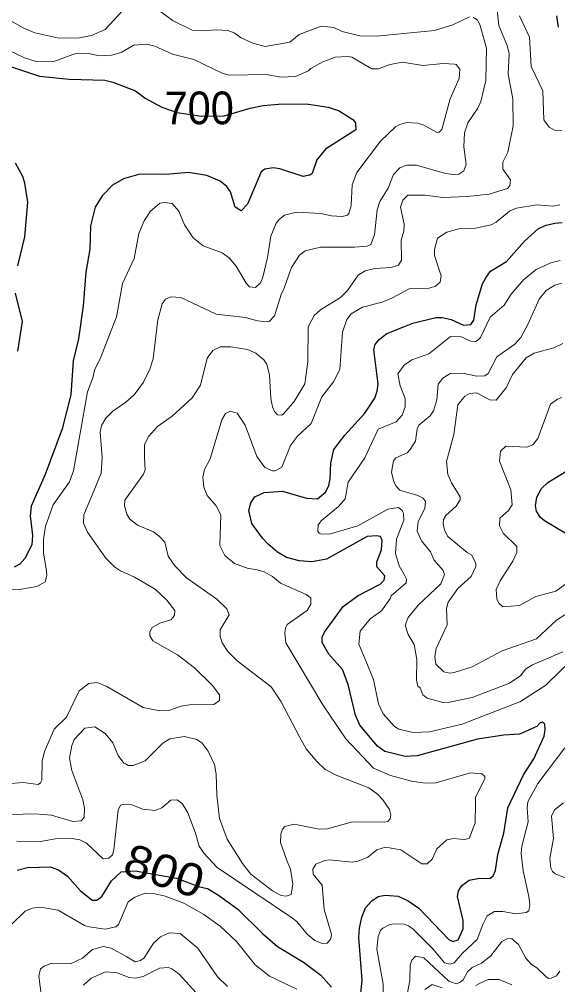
# Model space of a CAD drawing. Extents: x 294.2 to 320.3, y 7482.7 to 7510.7.
# Drawn here: x 316.982 to 318.3, y 7497.059 to 7499.421 of the extents above; entities that cross this region are included whole.
import ezdxf
from ezdxf.enums import TextEntityAlignment as Align

# ---------------------------------------------------------------- set-up
doc = ezdxf.new("R2010")
doc.units = 0
doc.header["$LTSCALE"] = 0.032
doc.layers.add('1', color=7, linetype='Continuous', lineweight=25)
doc.layers.add('2', color=7, linetype='Continuous', lineweight=13)
doc.layers.add('61', color=7, linetype='Continuous')

msp = doc.modelspace()

# ---------------------------------------------------------------- linework, layer by layer
at = {"layer": '1'}
for points in [[(318.3019, 7499.4013), (318.2974, 7499.4294)], [(316.9387, 7499.313), (317.0313, 7499.2818), (317.104, 7499.2742), (317.1916, 7499.2715), (317.2115, 7499.2672), (317.2664, 7499.2457), (317.2902, 7499.2274), (317.3313, 7499.2059), (317.3685, 7499.1924), (317.4284, 7499.1838), (317.4833, 7499.1843), (317.5471, 7499.2031), (317.5793, 7499.2096), (317.6264, 7499.2139), (317.6896, 7499.2128), (317.7384, 7499.2058), (317.765, 7499.1967), (317.7983, 7499.1757), (317.805, 7499.1671), (317.8055, 7499.1504), (317.7318, 7499.1031), (317.7102, 7499.0768), (317.6985, 7499.0434), (317.6935, 7499.0391), (317.6769, 7499.0364), (317.6197, 7499.0552), (317.6031, 7499.0574), (317.5831, 7499.0542), (317.5742, 7499.0472), (317.541, 7498.9686), (317.5249, 7498.9525), (317.5105, 7498.9611), (317.4989, 7498.9987), (317.49, 7499.0116), (317.4739, 7499.0245), (317.4412, 7499.039), (317.3963, 7499.046), (317.3408, 7499.0411), (317.2775, 7499.0421), (317.2375, 7499.0308), (317.2103, 7499.0152), (317.1853, 7498.9889), (317.1682, 7498.9614), (317.1565, 7498.9152), (317.1548, 7498.8582), (317.1454, 7498.8023), (317.1382, 7498.7195), (317.1271, 7498.6388), (317.1138, 7498.5851), (317.1083, 7498.5023), (317.0875, 7498.4193), (317.0452, 7498.3073), (317.0109, 7498.2299), (317.0092, 7498.2063), (317.0148, 7498.1584), (317.0131, 7498.1353), (316.9954, 7498.1014), (316.9837, 7498.088), (316.9699, 7498.0804)], [(316.9785, 7498.8178), (316.9962, 7498.8883), (317.0034, 7498.9738), (316.9962, 7499.0195), (316.9911, 7499.0361), (316.9731, 7499.0689)], [(318.1237, 7498.7884), (318.1353, 7498.8046), (318.1741, 7498.8282), (318.2185, 7498.8777), (318.2529, 7498.9089), (318.2718, 7498.9175), (318.2923, 7498.9224)], [(318.2923, 7498.9224), (318.3106, 7498.924)], [(317.909, 7497.2754), (317.9334, 7497.2646), (317.96, 7497.2463), (318.0333, 7497.1694), (318.0427, 7497.1651), (318.056, 7497.1689), (318.0682, 7497.1958), (318.0682, 7497.2162), (318.0549, 7497.2748), (318.0566, 7497.2888), (318.0655, 7497.3022), (318.0827, 7497.3146), (318.1043, 7497.3189), (318.1342, 7497.32), (318.142, 7497.3254), (318.1475, 7497.3388), (318.1536, 7497.3776), (318.1675, 7497.4297), (318.178, 7497.4921), (318.2158, 7497.5728), (318.2413, 7497.612), (318.2663, 7497.6669), (318.269, 7497.6836), (318.2679, 7497.6965), (318.2624, 7497.7013), (318.2557, 7497.6992), (318.2485, 7497.6906), (318.2064, 7497.6717), (318.1681, 7497.6696), (318.1032, 7497.6599), (317.9562, 7497.6191), (317.9263, 7497.6175), (317.8974, 7497.6245), (317.8763, 7497.6299), (317.8586, 7497.6428), (317.8153, 7497.6939), (317.8048, 7497.7181), (317.787, 7497.7934), (317.7731, 7497.83), (317.7393, 7497.8676), (317.7232, 7497.8966), (317.7232, 7497.9095), (317.7288, 7497.9219), (317.7744, 7497.9843), (317.8115, 7498.0112), (317.8654, 7498.0392), (317.8748, 7498.0489), (317.877, 7498.0591), (317.8571, 7498.0817), (317.8571, 7498.0936), (317.8682, 7498.1227), (317.8698, 7498.1457), (317.8665, 7498.1554), (317.8565, 7498.157), (317.8338, 7498.1554), (317.7339, 7498.1), (317.6979, 7498.0936), (317.6674, 7498.0957), (317.6363, 7498.1043), (317.6141, 7498.1172), (317.5914, 7498.1371), (317.577, 7498.1516), (317.5514, 7498.1871), (317.5442, 7498.2194), (317.5492, 7498.2382), (317.5586, 7498.2522), (317.5813, 7498.2635), (317.6263, 7498.2661), (317.685, 7498.2495), (317.7122, 7498.2479), (317.7327, 7498.2645), (317.7399, 7498.2801), (317.7432, 7498.2968), (317.7443, 7498.3349), (317.7521, 7498.3683), (317.7787, 7498.4033), (317.8281, 7498.4571), (317.8519, 7498.4942), (317.858, 7498.5114), (317.8602, 7498.5292), (317.8497, 7498.612), (317.853, 7498.6249), (317.8625, 7498.6373), (317.8819, 7498.6523), (317.9246, 7498.6695), (317.9456, 7498.6776), (318.0011, 7498.691), (318.0171, 7498.691), (318.0388, 7498.6862), (318.0693, 7498.6722), (318.087, 7498.6744), (318.0948, 7498.6846), (318.1004, 7498.7222), (318.1159, 7498.7739), (318.1237, 7498.7884)], [(316.9786, 7498.6092), (316.9897, 7498.6813), (316.973, 7498.7512)], [(318.3507, 7498.1441), (318.2674, 7498.1939), (318.2572, 7498.2028), (318.2476, 7498.2175), (318.2451, 7498.2303), (318.249, 7498.2514), (318.2603, 7498.2726), (318.2754, 7498.2877), (318.3283, 7498.3202)], [(316.9767, 7497.3393), (317.0022, 7497.3458), (317.0577, 7497.3473), (317.0782, 7497.3403), (317.0999, 7497.3248), (317.131, 7497.2898), (317.1609, 7497.2661), (317.172, 7497.2661), (317.1842, 7497.2753), (317.2081, 7497.3129), (317.2319, 7497.3355), (317.2657, 7497.3377), (317.3666, 7497.3194), (317.4232, 7497.2984), (317.4425, 7497.2949), (317.4696, 7497.2782), (317.5168, 7497.2437), (317.5772, 7497.1846), (317.6144, 7497.1528), (317.6776, 7497.1146), (317.7198, 7497.0824), (317.7458, 7497.0528)], [(317.8147, 7497.1974), (317.8202, 7497.2243), (317.8296, 7497.2474), (317.8452, 7497.2646), (317.8607, 7497.2748), (317.8779, 7497.278), (317.909, 7497.2754)], [(317.8174, 7497.0307), (317.8213, 7497.07), (317.813, 7497.1748), (317.8147, 7497.1974)]]:
    msp.add_lwpolyline(points, dxfattribs=at)
at = {"layer": '2'}
for points in [[(318.1493, 7499.4651), (318.1557, 7499.4057), (318.1758, 7499.3567), (318.1806, 7499.3362), (318.1787, 7499.2864), (318.1902, 7499.2263), (318.1908, 7499.1599), (318.1774, 7499.0954), (318.1651, 7499.0713), (318.1656, 7499.0541), (318.184, 7499.0279), (318.1823, 7499.0134), (318.1771, 7499.0068), (318.1318, 7498.9928), (318.0785, 7498.9875), (318.0184, 7498.9849), (317.975, 7498.9907), (317.9331, 7498.9907), (317.9205, 7498.9785), (317.9153, 7498.9612), (317.9239, 7498.9195), (317.9228, 7498.9024), (317.9165, 7498.8807), (317.9176, 7498.8317), (317.9102, 7498.8189), (317.8924, 7498.8133), (317.8524, 7498.8113), (317.8282, 7498.8056), (317.8115, 7498.7947), (317.7854, 7498.7577), (317.7682, 7498.7398), (317.719, 7498.7104), (317.7037, 7498.6964), (317.6889, 7498.6683), (317.6883, 7498.5828), (317.6813, 7498.5291), (317.6545, 7498.4857), (317.6296, 7498.4563)], [(317.2337, 7499.4408), (317.1922, 7499.3955), (317.1591, 7499.3808), (317.1297, 7499.3757), (317.0786, 7499.3744), (317.0199, 7499.3879), (316.9918, 7499.4), (316.9618, 7499.4166)], [(318.0836, 7499.4268), (318.0427, 7499.407), (317.998, 7499.3936), (317.8563, 7499.3795), (317.8154, 7499.3802), (317.772, 7499.391), (317.7516, 7499.4006), (317.7209, 7499.4038), (317.6673, 7499.3839), (317.6443, 7499.3644), (317.5842, 7499.354), (317.5536, 7499.3623), (317.5249, 7499.3757), (317.5077, 7499.3879), (317.4929, 7499.393), (317.4642, 7499.3948), (317.4285, 7499.3923), (317.4055, 7499.3942), (317.3589, 7499.4172), (317.311, 7499.4523)], [(318.0797, 7499.1676), (318.104, 7499.2034), (318.1116, 7499.22), (318.1238, 7499.271), (318.1257, 7499.3502), (318.1091, 7499.4076), (318.1034, 7499.4185)], [(318.1034, 7499.4185), (318.0925, 7499.4262)], [(318.3102, 7499.1483), (318.2918, 7499.1499), (318.2792, 7499.1566), (318.266, 7499.1744), (318.2631, 7499.2459), (318.235, 7499.3055), (318.231, 7499.377), (318.2061, 7499.4293)], [(317.8664, 7499.1229), (317.9029, 7499.1573), (317.9137, 7499.1637), (317.9303, 7499.1682), (317.9571, 7499.1663), (317.9725, 7499.1618), (318.0044, 7499.144), (318.0095, 7499.1446), (318.0165, 7499.151), (318.0363, 7499.2263), (318.0587, 7499.2761), (318.0599, 7499.2984), (318.051, 7499.31), (318.0472, 7499.3106), (318.0197, 7499.3125), (317.9699, 7499.308), (317.9201, 7499.3157), (317.8895, 7499.31), (317.8607, 7499.2998), (317.8448, 7499.2998), (317.7956, 7499.3278), (317.786, 7499.3297), (317.7554, 7499.3284), (317.7247, 7499.3164), (317.6953, 7499.3004), (317.6902, 7499.2946), (317.6583, 7499.2806), (317.6226, 7499.2793), (317.5868, 7499.2857), (317.4949, 7499.2838), (317.4783, 7499.2889), (317.4093, 7499.3221), (317.357, 7499.3355), (317.3142, 7499.3553), (317.2944, 7499.3598), (317.2625, 7499.3572), (317.2318, 7499.3393), (317.2076, 7499.333), (317.1782, 7499.331), (317.1514, 7499.3374), (317.1226, 7499.3381), (317.0664, 7499.3173), (317.021, 7499.3184), (316.9951, 7499.3268), (316.9561, 7499.3455)], [(316.9624, 7497.5516), (316.9918, 7497.5535), (317.0281, 7497.5491), (317.0339, 7497.5529), (317.0371, 7497.5599), (317.0384, 7497.6059), (317.0436, 7497.6296), (317.0677, 7497.6842), (317.0981, 7497.7137), (317.1284, 7497.7783), (317.1527, 7497.7961), (317.1731, 7497.7981), (317.1961, 7497.7884), (317.2855, 7497.7374), (317.3263, 7497.7291), (317.348, 7497.7297), (317.3787, 7497.7406), (317.3991, 7497.7437), (317.4585, 7497.7444), (317.4719, 7497.7546), (317.4725, 7497.7681), (317.4546, 7497.7917), (317.4112, 7497.8344), (317.3697, 7497.8657), (317.3091, 7497.9002), (317.3014, 7497.9124), (317.3014, 7497.9225), (317.3072, 7497.9328), (317.3263, 7497.9436), (317.3531, 7497.9519), (317.3621, 7497.9621), (317.3627, 7497.9749), (317.3436, 7497.9998), (317.3148, 7498.0266), (317.2638, 7498.056), (317.2299, 7498.0713), (317.2152, 7498.0815), (317.1942, 7498.1026), (317.1495, 7498.1665), (317.1393, 7498.1882), (317.1399, 7498.2086), (317.1577, 7498.2495), (317.1827, 7498.3108), (317.1852, 7498.3491), (317.1801, 7498.4104), (317.1833, 7498.427), (317.1942, 7498.4454), (317.2108, 7498.4621), (317.2427, 7498.4838), (317.2637, 7498.5023), (317.2861, 7498.533), (317.3014, 7498.5649), (317.3097, 7498.5904), (317.321, 7498.6859), (317.3319, 7498.7243), (317.3397, 7498.7359), (317.3531, 7498.7417), (317.3774, 7498.7398), (317.4642, 7498.6996), (317.5358, 7498.6912), (317.5655, 7498.6828), (317.5885, 7498.6806), (317.5937, 7498.6812), (317.6069, 7498.6951), (317.6235, 7498.7497), (317.6287, 7498.7586), (317.6481, 7498.8139), (317.6679, 7498.8439), (317.6819, 7498.8547), (317.7196, 7498.8636), (317.8026, 7498.863), (317.8333, 7498.8656), (317.8422, 7498.87), (317.8518, 7498.8931), (317.8582, 7498.9543), (317.8646, 7498.9748), (317.885, 7499.008), (317.8977, 7499.0412), (317.9137, 7499.0571), (317.9303, 7499.0635), (317.9546, 7499.0635), (318.0248, 7499.0437), (318.0443, 7499.0409), (318.0581, 7499.0421), (318.0702, 7499.0499), (318.0754, 7499.0654), (318.0702, 7499.1089), (318.072, 7499.1433), (318.0797, 7499.1676)], [(317.7723, 7498.9385), (317.785, 7498.9419), (317.789, 7498.9458), (317.7947, 7498.9653), (317.7969, 7499.0156), (317.8084, 7499.0463), (317.8664, 7499.1229)], [(316.965, 7498.026), (316.9879, 7498.0266), (317.025, 7498.033), (317.0454, 7498.0445), (317.0499, 7498.0605), (317.0486, 7498.0707), (317.0415, 7498.1154), (317.0415, 7498.1486), (317.046, 7498.1805), (317.0652, 7498.2329), (317.1048, 7498.2891), (317.115, 7498.3159), (317.1492, 7498.5092), (317.1624, 7498.5438), (317.1669, 7498.5647), (317.1802, 7498.5903), (317.2197, 7498.6926), (317.235, 7498.7743), (317.2631, 7498.8356), (317.2746, 7498.8969), (317.288, 7498.9275), (317.3021, 7498.9505), (317.3263, 7498.9709), (317.3378, 7498.9728), (317.3563, 7498.9703), (317.3723, 7498.9516), (317.3866, 7498.9181), (317.4073, 7498.8864), (317.4323, 7498.8669), (317.4783, 7498.8496), (317.4961, 7498.8375), (317.5127, 7498.8171), (317.5377, 7498.7749), (317.5453, 7498.7666), (317.56, 7498.7647), (317.5728, 7498.7762), (317.5785, 7498.7896), (317.59, 7498.8381), (317.5977, 7498.8905), (317.6111, 7498.9224), (317.6187, 7498.932), (317.6308, 7498.9415), (317.6609, 7498.9486), (317.7203, 7498.946), (317.7465, 7498.9402), (317.7723, 7498.9385)], [(317.4751, 7498.2086), (317.4636, 7498.2309), (317.4419, 7498.2559), (317.4336, 7498.2763), (317.431, 7498.3005), (317.4355, 7498.3197), (317.4489, 7498.3452), (317.4776, 7498.441), (317.4866, 7498.4563), (317.498, 7498.4621), (317.5153, 7498.4576), (317.5351, 7498.4282), (317.5632, 7498.3516), (317.583, 7498.3242), (317.6015, 7498.3158), (317.6085, 7498.3165), (317.6245, 7498.3254), (317.6455, 7498.3784), (317.6634, 7498.4008), (317.6966, 7498.4321), (317.7228, 7498.4972), (317.7515, 7498.5342), (317.7662, 7498.5642), (317.7732, 7498.6555), (317.7834, 7498.6862), (317.7943, 7498.7002), (317.8218, 7498.7162), (317.8703, 7498.729), (317.8958, 7498.7391), (317.9363, 7498.7618), (317.9852, 7498.7628), (318.0005, 7498.7679), (318.012, 7498.7781), (318.0146, 7498.7928), (317.9986, 7498.8432), (317.9986, 7498.8573), (318.0056, 7498.8854), (318.0287, 7498.9001), (318.058, 7498.9083), (318.0989, 7498.9096), (318.1372, 7498.9179), (318.1493, 7498.9243), (318.1819, 7498.9511), (318.1985, 7498.9588), (318.2483, 7498.9671), (318.2879, 7498.9639), (318.3051, 7498.9665)], [(318.3434, 7497.8625), (318.2706, 7497.7917), (318.209, 7497.752), (318.0661, 7497.6966), (317.9863, 7497.6779), (317.9461, 7497.6762), (317.911, 7497.6846), (317.9003, 7497.6908), (317.8728, 7497.7221), (317.8613, 7497.7463), (317.8492, 7497.8057), (317.8301, 7497.8511), (317.8128, 7497.8919), (317.8167, 7497.9238), (317.8409, 7497.9538), (317.8684, 7497.9736), (317.8907, 7498.0049), (317.8918, 7498.0105), (317.9289, 7498.0421), (317.9294, 7498.0513), (317.9239, 7498.0628), (317.9119, 7498.0839), (317.9027, 7498.1137), (317.9055, 7498.1488), (317.9228, 7498.1956), (317.9226, 7498.2124), (317.9195, 7498.2195), (317.9099, 7498.2264), (317.8837, 7498.2226), (317.8103, 7498.1817), (317.7438, 7498.1621), (317.7214, 7498.161), (317.7162, 7498.1637), (317.7128, 7498.1676), (317.7134, 7498.1838), (317.722, 7498.1944), (317.7633, 7498.2286), (317.7793, 7498.2475), (317.7868, 7498.2887), (317.8281, 7498.3478), (317.8601, 7498.4181), (317.9041, 7498.4359), (317.9188, 7498.4525), (317.9265, 7498.4729), (317.9265, 7498.4934), (317.9144, 7498.524), (317.9086, 7498.5534), (317.9239, 7498.5744), (317.9431, 7498.5878), (317.984, 7498.6025), (318.0376, 7498.6447), (318.0631, 7498.644), (318.0874, 7498.6332), (318.0982, 7498.6325), (318.1052, 7498.637), (318.111, 7498.6421), (318.1346, 7498.6919), (318.1685, 7498.7213), (318.1857, 7498.7481), (318.217, 7498.7839), (318.247, 7498.8087), (318.2828, 7498.8247), (318.3058, 7498.8311)], [(318.1946, 7498.6261), (318.2093, 7498.6421), (318.2278, 7498.676), (318.254, 7498.736), (318.2713, 7498.7571), (318.293, 7498.7704), (318.3096, 7498.7749)], [(317.5945, 7498.5502), (317.5881, 7498.577), (317.581, 7498.5878), (317.5613, 7498.6038), (317.5409, 7498.6128), (317.5, 7498.6197), (317.4744, 7498.6198), (317.4559, 7498.6102), (317.4419, 7498.5917), (317.4259, 7498.5259), (317.4049, 7498.4946), (317.3563, 7498.4499), (317.3206, 7498.425), (317.2982, 7498.4001), (317.2887, 7498.3797), (317.2887, 7498.3491), (317.2899, 7498.3184), (317.2861, 7498.3082), (317.2407, 7498.2443), (317.2395, 7498.2303), (317.2452, 7498.2099), (317.2529, 7498.1983), (317.2714, 7498.183), (317.311, 7498.1671), (317.3244, 7498.1562), (317.3384, 7498.1416), (317.3467, 7498.1077), (317.3627, 7498.0841), (317.3915, 7498.0547), (317.4655, 7498.0023), (317.4904, 7497.9787), (317.4955, 7497.9641), (317.4738, 7497.927), (317.4738, 7497.9111), (317.4783, 7497.8957), (317.4923, 7497.874), (317.5153, 7497.8517), (317.5983, 7497.7878), (317.6232, 7497.7515), (317.6679, 7497.6659), (317.6845, 7497.6365), (317.71, 7497.6052), (317.7311, 7497.5854), (317.7579, 7497.5714), (317.8377, 7497.5407), (317.8588, 7497.5254), (317.8716, 7497.5114), (317.8882, 7497.4878), (317.8914, 7497.4744), (317.8901, 7497.4647), (317.8837, 7497.4584), (317.8754, 7497.4564), (317.7975, 7497.4577), (317.7362, 7497.4405), (317.7158, 7497.4398), (317.6545, 7497.452), (317.6322, 7497.4462), (317.6264, 7497.4399), (317.6219, 7497.4271), (317.6213, 7497.4067), (317.6372, 7497.3626), (317.6455, 7497.3422), (317.6518, 7497.3049), (317.6472, 7497.2799), (317.6351, 7497.276), (317.6231, 7497.2771), (317.6021, 7497.2892), (317.5489, 7497.3295), (317.5288, 7497.3556), (317.4909, 7497.4155), (317.4725, 7497.4654), (317.4655, 7497.5229), (317.4642, 7497.5739), (317.4598, 7497.5982), (317.4444, 7497.6301), (317.4298, 7497.6499), (317.417, 7497.6589), (317.3863, 7497.6665), (317.3506, 7497.6607), (317.3333, 7497.6499), (317.2906, 7497.6071), (317.2612, 7497.595), (317.249, 7497.595), (317.2427, 7497.5995), (317.2382, 7497.6007), (317.2241, 7497.6199), (317.2108, 7497.6506), (317.1922, 7497.6735), (317.1673, 7497.6901), (317.1425, 7497.687), (317.1162, 7497.6589), (317.1105, 7497.6442), (317.1054, 7497.6135), (317.1112, 7497.5829), (317.138, 7497.5114)], [(318.3121, 7497.8734), (318.2378, 7497.8418), (318.2212, 7497.8307), (318.2091, 7497.8154), (318.1821, 7497.7964), (318.0903, 7497.7619), (318.0346, 7497.7502), (318.0185, 7497.7497), (317.9807, 7497.7597), (317.9699, 7497.7681), (317.9629, 7497.7853), (317.9571, 7497.7897), (317.9539, 7497.8044), (317.9552, 7497.8549), (317.9482, 7497.8912), (317.9341, 7497.9162), (317.9271, 7497.9366), (317.9277, 7497.943), (317.9335, 7497.9576), (317.9584, 7497.9877), (318.014, 7498.0394), (318.0229, 7498.0624), (318.0197, 7498.0726), (317.9974, 7498.0975), (317.9884, 7498.1179), (317.9667, 7498.1448), (317.9558, 7498.169), (317.9584, 7498.192), (317.9744, 7498.2239), (317.9763, 7498.2412), (317.9705, 7498.2495), (317.9571, 7498.2558), (317.9137, 7498.2693), (317.9035, 7498.2795), (317.8978, 7498.2929), (317.8927, 7498.3133), (317.8978, 7498.3408), (317.9035, 7498.3477), (317.931, 7498.3605), (317.9386, 7498.3682), (317.952, 7498.3886), (317.9558, 7498.4193), (317.9597, 7498.4276), (317.9878, 7498.4506), (317.9961, 7498.4627), (318.0043, 7498.4895), (318.0076, 7498.5285), (318.0184, 7498.5431), (318.0363, 7498.5546), (318.067, 7498.5553), (318.1017, 7498.5477), (318.1218, 7498.5488), (318.1298, 7498.5539), (318.1511, 7498.5951), (318.1946, 7498.6261)], [(318.3172, 7497.9641), (318.2968, 7497.9506), (318.2476, 7497.9053), (318.164, 7497.876), (318.09, 7497.837), (318.0465, 7497.8229), (318.0357, 7497.821), (318.021, 7497.8242), (318.0018, 7497.8434), (317.9993, 7497.8613), (318.0025, 7497.8817), (318.0293, 7497.9392), (318.0278, 7497.9796), (318.0319, 7497.9946), (318.0554, 7498.0286), (318.0881, 7498.0581), (318.0996, 7498.0823), (318.0996, 7498.0895), (318.0892, 7498.1101), (318.0778, 7498.1162), (318.0307, 7498.1552), (318.0226, 7498.1708), (318.0191, 7498.1869), (318.0203, 7498.1971), (318.0261, 7498.2073), (318.051, 7498.2296), (318.0612, 7498.245), (318.0612, 7498.2526), (318.0395, 7498.2865), (318.0306, 7498.3069), (318.028, 7498.3389), (318.0452, 7498.4053), (318.0554, 7498.478), (318.0727, 7498.4991), (318.0836, 7498.5055), (318.1014, 7498.5068), (318.1333, 7498.4895), (318.1493, 7498.4889), (318.1736, 7498.5195), (318.1889, 7498.5521), (318.2228, 7498.5929), (318.2419, 7498.6044), (318.2904, 7498.6172), (318.3121, 7498.6274)], [(317.6296, 7498.4563), (317.6245, 7498.4525), (317.6143, 7498.4531), (317.6066, 7498.4614), (317.6021, 7498.4729), (317.5977, 7498.4934), (317.5945, 7498.5502)], [(318.3453, 7498.0586), (318.2955, 7498.0221), (318.2463, 7498.0088), (318.2062, 7497.987), (318.1652, 7497.9838), (318.1557, 7497.9921), (318.1506, 7498.003), (318.1493, 7498.026), (318.1589, 7498.0471), (318.1902, 7498.095), (318.1997, 7498.1166), (318.1997, 7498.1307), (318.1659, 7498.1639), (318.1576, 7498.1818), (318.1583, 7498.2003), (318.1793, 7498.2188), (318.1882, 7498.2328), (318.1851, 7498.2699), (318.157, 7498.3395), (318.1601, 7498.3644), (318.173, 7498.3765), (318.224, 7498.374), (318.2387, 7498.3797), (318.2508, 7498.395), (318.2821, 7498.4793), (318.2994, 7498.4914), (318.3096, 7498.4953)], [(317.5817, 7498.0688), (317.5613, 7498.0752), (317.5421, 7498.077), (317.5089, 7498.0898), (317.4853, 7498.109), (317.4732, 7498.1332), (317.4751, 7498.2086)], [(316.9764, 7497.4099), (317.0301, 7497.4086), (317.0697, 7497.4162), (317.1067, 7497.4175), (317.1303, 7497.4137), (317.1469, 7497.4054), (317.1877, 7497.367), (317.2012, 7497.369), (317.2101, 7497.3766), (317.2133, 7497.3888), (317.2241, 7497.4859), (317.2299, 7497.498), (317.2369, 7497.5005), (317.2574, 7497.4993), (317.2842, 7497.4884), (317.3148, 7497.4852), (317.3308, 7497.4922), (317.3531, 7497.5107), (317.3684, 7497.5113), (317.3806, 7497.5025), (317.3946, 7497.4795), (317.4138, 7497.4297), (317.4221, 7497.3977), (317.4336, 7497.3811), (317.4668, 7497.346), (317.6511, 7497.2221), (317.6614, 7497.2138), (317.6867, 7497.1826), (317.7056, 7497.1672), (317.7234, 7497.1602), (317.7356, 7497.1609), (317.7445, 7497.1717), (317.7464, 7497.1819), (317.7279, 7497.2432), (317.7234, 7497.3026), (317.7017, 7497.3294), (317.7004, 7497.3422), (317.7081, 7497.3537), (317.7299, 7497.3632), (317.7401, 7497.3645), (317.7969, 7497.3588), (317.8116, 7497.3613), (317.8352, 7497.3709), (317.8575, 7497.3888), (317.878, 7497.3958), (317.9156, 7497.3894), (317.9673, 7497.355), (317.9807, 7497.355), (317.9929, 7497.3664), (318.004, 7497.3916), (318.0287, 7497.4133), (318.0447, 7497.4172), (318.0712, 7497.4144), (318.0832, 7497.4172), (318.0976, 7497.455), (318.0982, 7497.5024), (318.0982, 7497.5178), (318.1212, 7497.5625), (318.1212, 7497.5682), (318.1142, 7497.5752), (318.0861, 7497.5771), (318.0018, 7497.5529), (317.975, 7497.5522), (317.9418, 7497.5567), (317.8907, 7497.5708), (317.8486, 7497.5886), (317.7816, 7497.6608), (317.7254, 7497.7438), (317.6347, 7497.8951), (317.6322, 7497.9187), (317.6334, 7497.9321), (317.6379, 7497.9404), (317.6864, 7497.9749), (317.696, 7497.9902), (317.6953, 7498.0055), (317.6839, 7498.0139), (317.6213, 7498.0413), (317.6022, 7498.0579), (317.5817, 7498.0688)], [(318.2106, 7497.3799), (318.2119, 7497.3977), (318.2278, 7497.4578), (318.2247, 7497.4922), (318.2265, 7497.5069), (318.2508, 7497.551), (318.3172, 7497.6384)], [(317.138, 7497.5114), (317.1418, 7497.491), (317.1411, 7497.4679), (317.1335, 7497.4597), (317.1131, 7497.4584), (317.0607, 7497.4737), (317.0199, 7497.4769)], [(318.3262, 7497.3172), (318.2936, 7497.33), (318.2872, 7497.3364), (318.2827, 7497.3441), (318.2802, 7497.3684), (318.2898, 7497.4169), (318.2847, 7497.4711), (318.2917, 7497.4871), (318.314, 7497.5037)], [(317.0199, 7497.4769), (316.9337, 7497.475)], [(318.1972, 7497.2324), (318.2227, 7497.2355), (318.2291, 7497.24), (318.2316, 7497.2547), (318.2291, 7497.2752), (318.215, 7497.3377), (318.2106, 7497.3799)], [(316.963, 7497.2062), (316.9969, 7497.2388), (317.0141, 7497.2464), (317.0339, 7497.249), (317.0773, 7497.2419), (317.1418, 7497.2043), (317.1533, 7497.201), (317.1923, 7497.1953), (317.2184, 7497.2004), (317.2248, 7497.2062), (317.2484, 7497.2617), (317.265, 7497.2732), (317.2899, 7497.2834), (317.311, 7497.2822), (317.3391, 7497.2758), (317.3851, 7497.2585), (317.4336, 7497.2311), (317.4738, 7497.2023), (317.514, 7497.1647), (317.5593, 7497.1078), (317.5944, 7497.0804), (317.661, 7497.0485)], [(317.8728, 7497.0223), (317.8728, 7497.0606), (317.8575, 7497.1462), (317.8601, 7497.1768), (317.8664, 7497.1921), (317.8716, 7497.1972), (317.8888, 7497.2062), (317.901, 7497.2081), (317.9239, 7497.2074), (317.9348, 7497.203), (317.9463, 7497.1953), (317.9941, 7497.1468), (318.0223, 7497.1123), (318.0363, 7497.1091), (318.0465, 7497.1123), (318.067, 7497.1366), (318.1027, 7497.1698), (318.1167, 7497.2068), (318.127, 7497.2273), (318.1448, 7497.2381), (318.1653, 7497.2381), (318.1972, 7497.2324)], [(317.039, 7497.0108), (317.03, 7497.0798), (317.0345, 7497.0983), (317.0428, 7497.1047), (317.0607, 7497.1117), (317.1092, 7497.1111), (317.1373, 7497.1238), (317.1616, 7497.1449), (317.1871, 7497.1525), (317.2069, 7497.1487), (317.2452, 7497.127), (317.2657, 7497.1155), (317.2791, 7497.1181), (317.288, 7497.1251), (317.311, 7497.1609), (317.3276, 7497.1762), (317.3486, 7497.1864), (317.3755, 7497.1844), (317.4195, 7497.1487), (317.4674, 7497.0785), (317.4917, 7497.0548)], [(317.931, 7497.0351), (317.9379, 7497.0696), (317.9386, 7497.1066), (317.9425, 7497.1194), (317.952, 7497.1289), (317.9724, 7497.1251), (318.0331, 7497.0676), (318.0516, 7497.0613), (318.0606, 7497.0644), (318.0682, 7497.0714), (318.0791, 7497.0906), (318.0906, 7497.1015), (318.1129, 7497.1117), (318.1359, 7497.1295), (318.1627, 7497.1647), (318.1774, 7497.1724), (318.1876, 7497.1717), (318.2036, 7497.1577), (318.2221, 7497.1238)], [(317.1392, 7497.058), (317.1584, 7497.0753), (317.1935, 7497.0906), (317.2216, 7497.0881), (317.2509, 7497.0772), (317.2663, 7497.0753), (317.2855, 7497.0791), (317.3257, 7497.0996), (317.3468, 7497.1014), (317.3557, 7497.0983), (317.3735, 7497.0849), (317.415, 7497.0395)], [(318.2221, 7497.1238), (318.2348, 7497.1091), (318.2489, 7497.1002), (318.2713, 7497.0785), (318.277, 7497.0746), (318.284, 7497.0753), (318.2968, 7497.0811)], [(318.2968, 7497.0811), (318.3051, 7497.0925)], [(317.9744, 7497.0472), (317.9922, 7497.06), (318.0172, 7497.0517)], [(318.0995, 7497.0574), (318.1084, 7497.0625), (318.1295, 7497.0715), (318.1564, 7497.0715), (318.1876, 7497.0587)]]:
    msp.add_lwpolyline(points, dxfattribs=at)

# ---------------------------------------------------------------- texts
at = {"layer": '61', "width": 0.95}
msp.add_text('700', height=0.08, dxfattribs=at).set_placement((317.4224, 7499.164), align=Align.CENTER)
at = {"layer": '61', "width": 1.1}
msp.add_text('800', height=0.08, rotation=341.686, dxfattribs=at).set_placement((317.3242, 7497.2997), align=Align.CENTER)

doc.saveas('drawing.dxf')
